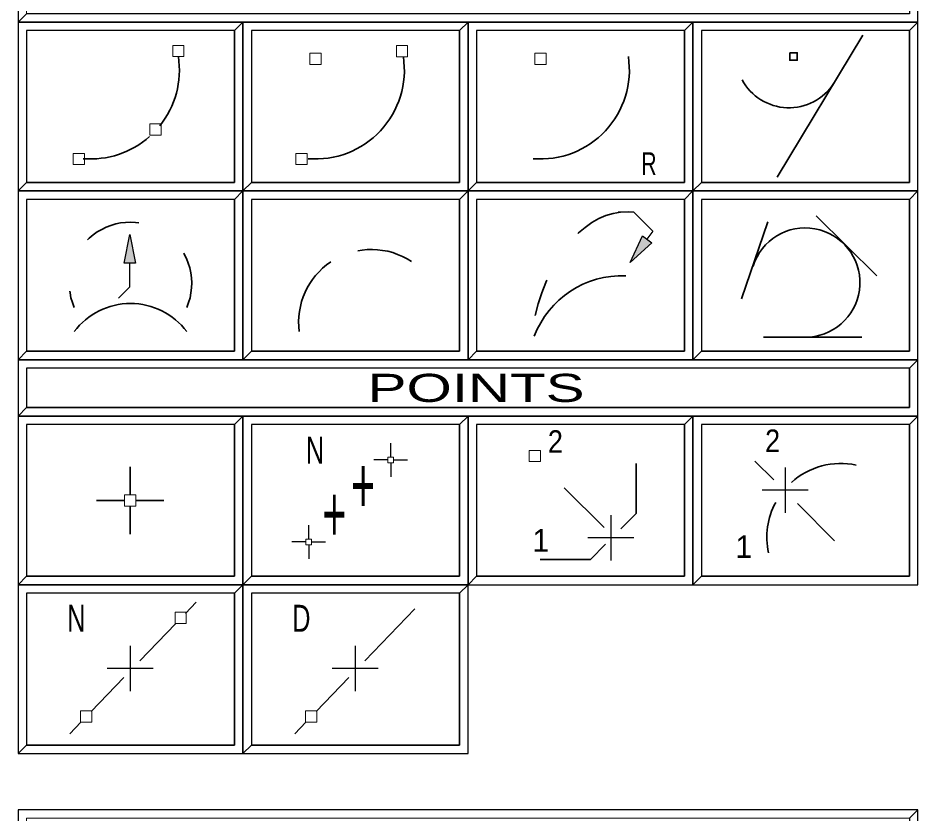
# Model space of a CAD drawing. Extents: x 95906.8 to 95923.6, y 90964.8 to 90972.8.
# Drawn here: x 95910.832 to 95912.432, y 90967.254 to 90968.669 of the extents above; entities that cross this region are included whole.
import ezdxf
from ezdxf.enums import TextEntityAlignment as Align

# ---------------------------------------------------------------- set-up
doc = ezdxf.new("R2010")
doc.units = 0
doc.header["$LTSCALE"] = 0.019
doc.linetypes.add('MEDIUM_DASHED', pattern=[4.5, 3, -1.5])
for name, color, linetype, lineweight in [('1', 7, 'Continuous', 25), ('11', 7, 'Continuous', 25), ('12', 7, 'Continuous', 25), ('17', 7, 'Continuous', 25), ('2', 7, 'Continuous', 13), ('3', 7, 'Continuous', 25), ('6', 7, 'Continuous', 35), ('7', 7, 'Continuous', 35)]:
    doc.layers.add(name, color=color, linetype=linetype, lineweight=lineweight)

msp = doc.modelspace()

# ---------------------------------------------------------------- hatches: boundary and pattern name
at = {"layer": '6'}
for points in [[(95911.0204, 90968.2331), (95911.0306, 90968.2843), (95911.0408, 90968.2331)], [(95911.9585, 90968.2697), (95911.92, 90968.2344), (95911.9421, 90968.2817)]]:
    msp.add_hatch(color=256, dxfattribs=at).paths.add_polyline_path(points)

# ---------------------------------------------------------------- linework, layer by layer
at = {"layer": '1'}
for points in [[(95910.8318, 90968.6617), (95912.4318, 90968.6617), (95912.4318, 90968.7617), (95910.8318, 90968.7617)], [(95910.8318, 90968.3617), (95911.2318, 90968.3617), (95911.2318, 90968.6617), (95910.8318, 90968.6617)], [(95911.2318, 90968.3617), (95911.6318, 90968.3617), (95911.6318, 90968.6617), (95911.2318, 90968.6617)], [(95911.6318, 90968.3617), (95912.0318, 90968.3617), (95912.0318, 90968.6617), (95911.6318, 90968.6617)], [(95912.0318, 90968.3617), (95912.4318, 90968.3617), (95912.4318, 90968.6617), (95912.0318, 90968.6617)], [(95910.8318, 90968.0617), (95911.2318, 90968.0617), (95911.2318, 90968.3617), (95910.8318, 90968.3617)], [(95911.2318, 90968.0617), (95911.6318, 90968.0617), (95911.6318, 90968.3617), (95911.2318, 90968.3617)], [(95911.6318, 90968.0617), (95912.0318, 90968.0617), (95912.0318, 90968.3617), (95911.6318, 90968.3617)], [(95912.0318, 90968.0617), (95912.4318, 90968.0617), (95912.4318, 90968.3617), (95912.0318, 90968.3617)], [(95910.8318, 90967.9617), (95912.4318, 90967.9617), (95912.4318, 90968.0617), (95910.8318, 90968.0617)], [(95910.8318, 90967.6617), (95911.2318, 90967.6617), (95911.2318, 90967.9617), (95910.8318, 90967.9617)], [(95911.2318, 90967.6617), (95911.6318, 90967.6617), (95911.6318, 90967.9617), (95911.2318, 90967.9617)], [(95911.6318, 90967.6617), (95912.0318, 90967.6617), (95912.0318, 90967.9617), (95911.6318, 90967.9617)], [(95912.0318, 90967.6617), (95912.4318, 90967.6617), (95912.4318, 90967.9617), (95912.0318, 90967.9617)], [(95910.8318, 90967.3617), (95911.2318, 90967.3617), (95911.2318, 90967.6617), (95910.8318, 90967.6617)], [(95911.2318, 90967.3617), (95911.6318, 90967.3617), (95911.6318, 90967.6617), (95911.2318, 90967.6617)], [(95910.8318, 90967.1617), (95912.4318, 90967.1617), (95912.4318, 90967.2617), (95910.8318, 90967.2617)]]:
    msp.add_lwpolyline(points, close=True, dxfattribs=at)
at = {"layer": '11'}
for points in [[(95911.2468, 90968.3767), (95911.6168, 90968.3767), (95911.6168, 90968.6467), (95911.2468, 90968.6467)], [(95911.6468, 90968.3767), (95912.0168, 90968.3767), (95912.0168, 90968.6467), (95911.6468, 90968.6467)], [(95912.0468, 90968.3767), (95912.4168, 90968.3767), (95912.4168, 90968.6467), (95912.0468, 90968.6467)], [(95910.8468, 90968.0767), (95911.2168, 90968.0767), (95911.2168, 90968.3467), (95910.8468, 90968.3467)], [(95911.2468, 90968.0767), (95911.6168, 90968.0767), (95911.6168, 90968.3467), (95911.2468, 90968.3467)], [(95911.6468, 90968.0767), (95912.0168, 90968.0767), (95912.0168, 90968.3467), (95911.6468, 90968.3467)], [(95912.0468, 90968.0767), (95912.4168, 90968.0767), (95912.4168, 90968.3467), (95912.0468, 90968.3467)], [(95911.2468, 90967.6767), (95911.6168, 90967.6767), (95911.6168, 90967.9467), (95911.2468, 90967.9467)], [(95911.6468, 90967.6767), (95912.0168, 90967.6767), (95912.0168, 90967.9467), (95911.6468, 90967.9467)], [(95912.0468, 90967.6767), (95912.4168, 90967.6767), (95912.4168, 90967.9467), (95912.0468, 90967.9467)], [(95910.8468, 90967.3767), (95911.2168, 90967.3767), (95911.2168, 90967.6467), (95910.8468, 90967.6467)], [(95911.2468, 90967.3767), (95911.6168, 90967.3767), (95911.6168, 90967.6467), (95911.2468, 90967.6467)]]:
    msp.add_lwpolyline(points, close=True, dxfattribs=at)
at = {"layer": '12'}
for points in [[(95910.8468, 90968.3767), (95911.2168, 90968.3767), (95911.2168, 90968.6467), (95910.8468, 90968.6467)], [(95910.8468, 90967.6767), (95911.2168, 90967.6767), (95911.2168, 90967.9467), (95910.8468, 90967.9467)]]:
    msp.add_lwpolyline(points, close=True, dxfattribs=at)
at = {"layer": '17'}
msp.add_lwpolyline([(95910.8468, 90967.9767), (95912.4168, 90967.9767), (95912.4168, 90968.0467), (95910.8468, 90968.0467)], close=True, dxfattribs=at)
at = {"layer": '2'}
for points in [[(95910.8318, 90968.7617), (95910.8318, 90968.6617), (95910.8468, 90968.6767), (95910.8468, 90968.7467), (95912.4168, 90968.7467), (95912.4318, 90968.7617)], [(95910.8318, 90968.6617), (95910.8318, 90968.3617), (95910.8468, 90968.3767), (95910.8468, 90968.6467), (95911.2168, 90968.6467), (95911.2318, 90968.6617)], [(95911.2318, 90968.6617), (95911.2318, 90968.3617), (95911.2468, 90968.3767), (95911.2468, 90968.6467), (95911.6168, 90968.6467), (95911.6318, 90968.6617)], [(95911.6318, 90968.6617), (95911.6318, 90968.3617), (95911.6468, 90968.3767), (95911.6468, 90968.6467), (95912.0168, 90968.6467), (95912.0318, 90968.6617)], [(95912.0318, 90968.6617), (95912.0318, 90968.3617), (95912.0468, 90968.3767), (95912.0468, 90968.6467), (95912.4168, 90968.6467), (95912.4318, 90968.6617)], [(95910.8318, 90968.3617), (95910.8318, 90968.0617), (95910.8468, 90968.0767), (95910.8468, 90968.3467), (95911.2168, 90968.3467), (95911.2318, 90968.3617)], [(95911.2318, 90968.3617), (95911.2318, 90968.0617), (95911.2468, 90968.0767), (95911.2468, 90968.3467), (95911.6168, 90968.3467), (95911.6318, 90968.3617)], [(95911.6318, 90968.3617), (95911.6318, 90968.0617), (95911.6468, 90968.0767), (95911.6468, 90968.3467), (95912.0168, 90968.3467), (95912.0318, 90968.3617)], [(95912.0318, 90968.3617), (95912.0318, 90968.0617), (95912.0468, 90968.0767), (95912.0468, 90968.3467), (95912.4168, 90968.3467), (95912.4318, 90968.3617)], [(95910.8318, 90968.0617), (95910.8318, 90967.9617), (95910.8468, 90967.9767), (95910.8468, 90968.0467), (95912.4168, 90968.0467), (95912.4318, 90968.0617)], [(95910.8318, 90967.9617), (95910.8318, 90967.6617), (95910.8468, 90967.6767), (95910.8468, 90967.9467), (95911.2168, 90967.9467), (95911.2318, 90967.9617)], [(95911.2318, 90967.9617), (95911.2318, 90967.6617), (95911.2468, 90967.6767), (95911.2468, 90967.9467), (95911.6168, 90967.9467), (95911.6318, 90967.9617)], [(95911.6318, 90967.9617), (95911.6318, 90967.6617), (95911.6468, 90967.6767), (95911.6468, 90967.9467), (95912.0168, 90967.9467), (95912.0318, 90967.9617)], [(95912.0318, 90967.9617), (95912.0318, 90967.6617), (95912.0468, 90967.6767), (95912.0468, 90967.9467), (95912.4168, 90967.9467), (95912.4318, 90967.9617)], [(95910.8318, 90967.6617), (95910.8318, 90967.3617), (95910.8468, 90967.3767), (95910.8468, 90967.6467), (95911.2168, 90967.6467), (95911.2318, 90967.6617)], [(95911.2318, 90967.6617), (95911.2318, 90967.3617), (95911.2468, 90967.3767), (95911.2468, 90967.6467), (95911.6168, 90967.6467), (95911.6318, 90967.6617)], [(95910.8318, 90967.2617), (95910.8318, 90967.1617), (95910.8468, 90967.1767), (95910.8468, 90967.2467), (95912.4168, 90967.2467), (95912.4318, 90967.2617)]]:
    msp.add_lwpolyline(points, close=True, dxfattribs=at)
at = {"layer": '3'}
for points in [[(95910.8318, 90968.6617), (95912.4318, 90968.6617), (95912.4318, 90968.7617), (95912.4168, 90968.7467), (95912.4168, 90968.6767), (95910.8468, 90968.6767)], [(95910.8318, 90968.3617), (95911.2318, 90968.3617), (95911.2318, 90968.6617), (95911.2168, 90968.6467), (95911.2168, 90968.3767), (95910.8468, 90968.3767)], [(95911.2318, 90968.3617), (95911.6318, 90968.3617), (95911.6318, 90968.6617), (95911.6168, 90968.6467), (95911.6168, 90968.3767), (95911.2468, 90968.3767)], [(95911.6318, 90968.3617), (95912.0318, 90968.3617), (95912.0318, 90968.6617), (95912.0168, 90968.6467), (95912.0168, 90968.3767), (95911.6468, 90968.3767)], [(95912.0318, 90968.3617), (95912.4318, 90968.3617), (95912.4318, 90968.6617), (95912.4168, 90968.6467), (95912.4168, 90968.3767), (95912.0468, 90968.3767)], [(95910.8318, 90968.0617), (95911.2318, 90968.0617), (95911.2318, 90968.3617), (95911.2168, 90968.3467), (95911.2168, 90968.0767), (95910.8468, 90968.0767)], [(95911.2318, 90968.0617), (95911.6318, 90968.0617), (95911.6318, 90968.3617), (95911.6168, 90968.3467), (95911.6168, 90968.0767), (95911.2468, 90968.0767)], [(95911.6318, 90968.0617), (95912.0318, 90968.0617), (95912.0318, 90968.3617), (95912.0168, 90968.3467), (95912.0168, 90968.0767), (95911.6468, 90968.0767)], [(95912.0318, 90968.0617), (95912.4318, 90968.0617), (95912.4318, 90968.3617), (95912.4168, 90968.3467), (95912.4168, 90968.0767), (95912.0468, 90968.0767)], [(95910.8318, 90967.9617), (95912.4318, 90967.9617), (95912.4318, 90968.0617), (95912.4168, 90968.0467), (95912.4168, 90967.9767), (95910.8468, 90967.9767)], [(95910.8318, 90967.6617), (95911.2318, 90967.6617), (95911.2318, 90967.9617), (95911.2168, 90967.9467), (95911.2168, 90967.6767), (95910.8468, 90967.6767)], [(95911.2318, 90967.6617), (95911.6318, 90967.6617), (95911.6318, 90967.9617), (95911.6168, 90967.9467), (95911.6168, 90967.6767), (95911.2468, 90967.6767)], [(95911.6318, 90967.6617), (95912.0318, 90967.6617), (95912.0318, 90967.9617), (95912.0168, 90967.9467), (95912.0168, 90967.6767), (95911.6468, 90967.6767)], [(95912.0318, 90967.6617), (95912.4318, 90967.6617), (95912.4318, 90967.9617), (95912.4168, 90967.9467), (95912.4168, 90967.6767), (95912.0468, 90967.6767)], [(95910.8318, 90967.3617), (95911.2318, 90967.3617), (95911.2318, 90967.6617), (95911.2168, 90967.6467), (95911.2168, 90967.3767), (95910.8468, 90967.3767)], [(95911.2318, 90967.3617), (95911.6318, 90967.3617), (95911.6318, 90967.6617), (95911.6168, 90967.6467), (95911.6168, 90967.3767), (95911.2468, 90967.3767)], [(95910.8318, 90967.1617), (95912.4318, 90967.1617), (95912.4318, 90967.2617), (95912.4168, 90967.2467), (95912.4168, 90967.1767), (95910.8468, 90967.1767)]]:
    msp.add_lwpolyline(points, close=True, dxfattribs=at)
at = {"layer": '6'}
for p, q in [((95912.1815, 90968.3864), (95912.334, 90968.6387)), ((95912.1182, 90968.1698), (95912.1646, 90968.3071)), ((95912.251, 90968.3178), (95912.3589, 90968.2108)), ((95912.3322, 90968.102), (95912.1574, 90968.102)), ((95912.142, 90967.8817), (95912.1756, 90967.8481)), ((95911.0312, 90967.8216), (95911.0312, 90967.8716)), ((95911.0212, 90967.8116), (95910.9712, 90967.8116)), ((95911.0412, 90967.8116), (95911.0912, 90967.8116)), ((95911.0312, 90967.8016), (95911.0312, 90967.7516)), ((95912.2836, 90967.74), (95912.2176, 90967.8061)), ((95911.1484, 90967.6305), (95911.1295, 90967.6108)), ((95911.4485, 90967.5266), (95911.537, 90967.6188)), ((95911.0485, 90967.5266), (95911.1117, 90967.5924)), ((95910.9617, 90967.4363), (95911.02, 90967.4969)), ((95911.3617, 90967.4363), (95911.42, 90967.4969)), ((95910.9238, 90967.3969), (95910.9434, 90967.4173)), ((95911.3238, 90967.3969), (95911.3434, 90967.4173))]:
    msp.add_line(p, q, dxfattribs=at)
at = {"layer": '6', "lineweight": 25}
for p, q in [((95911.4944, 90967.8886), (95911.4944, 90967.9136)), ((95911.4894, 90967.8836), (95911.4644, 90967.8836)), ((95911.4944, 90967.8786), (95911.4944, 90967.8536)), ((95911.4994, 90967.8836), (95911.5244, 90967.8836)), ((95912.1957, 90967.8699), (95912.1957, 90967.7896)), ((95912.1548, 90967.8305), (95912.2367, 90967.8305)), ((95911.8855, 90967.7853), (95911.8855, 90967.705)), ((95911.3486, 90967.7428), (95911.3486, 90967.7678)), ((95911.8446, 90967.7459), (95911.9265, 90967.7459)), ((95911.3436, 90967.7378), (95911.3186, 90967.7378)), ((95911.3486, 90967.7328), (95911.3486, 90967.7078)), ((95911.3536, 90967.7378), (95911.3786, 90967.7378)), ((95911.031, 90967.553), (95911.031, 90967.4727)), ((95911.431, 90967.553), (95911.431, 90967.4727)), ((95910.9901, 90967.5136), (95911.072, 90967.5136)), ((95911.3901, 90967.5136), (95911.472, 90967.5136))]:
    msp.add_line(p, q, dxfattribs=at)
at = {"layer": '6', "linetype": 'MEDIUM_DASHED'}
msp.add_line((95911.8738, 90967.7635), (95911.7588, 90967.8783), dxfattribs=at)
at = {"layer": '6', "lineweight": 13}
for points in [[(95911.1069, 90968.6005), (95911.1269, 90968.6005), (95911.1269, 90968.6205), (95911.1069, 90968.6205)], [(95911.5044, 90968.6001), (95911.5244, 90968.6001), (95911.5244, 90968.6201), (95911.5044, 90968.6201)], [(95911.3508, 90968.5865), (95911.3708, 90968.5865), (95911.3708, 90968.6065), (95911.3508, 90968.6065)], [(95911.7508, 90968.5865), (95911.7708, 90968.5865), (95911.7708, 90968.6065), (95911.7508, 90968.6065)], [(95911.0662, 90968.461), (95911.0862, 90968.461), (95911.0862, 90968.481), (95911.0662, 90968.481)], [(95910.9298, 90968.4086), (95910.9498, 90968.4086), (95910.9498, 90968.4286), (95910.9298, 90968.4286)], [(95911.326, 90968.4086), (95911.346, 90968.4086), (95911.346, 90968.4286), (95911.326, 90968.4286)], [(95911.4894, 90967.8786), (95911.4994, 90967.8786), (95911.4994, 90967.8886), (95911.4894, 90967.8886)], [(95911.7407, 90967.8806), (95911.7607, 90967.8806), (95911.7607, 90967.9006), (95911.7407, 90967.9006)], [(95911.0212, 90967.8016), (95911.0412, 90967.8016), (95911.0412, 90967.8216), (95911.0212, 90967.8216)], [(95911.3436, 90967.7328), (95911.3536, 90967.7328), (95911.3536, 90967.7428), (95911.3436, 90967.7428)], [(95911.111, 90967.5931), (95911.131, 90967.5931), (95911.131, 90967.6131), (95911.111, 90967.6131)], [(95910.9432, 90967.4175), (95910.9632, 90967.4175), (95910.9632, 90967.4375), (95910.9432, 90967.4375)], [(95911.3432, 90967.4175), (95911.3632, 90967.4175), (95911.3632, 90967.4375), (95911.3432, 90967.4375)]]:
    msp.add_lwpolyline(points, close=True, dxfattribs=at)
at = {"layer": '6'}
msp.add_lwpolyline([(95912.2038, 90968.6075), (95912.2172, 90968.6075), (95912.2172, 90968.5942), (95912.2038, 90968.5942)], close=True, dxfattribs=at)
at = {"layer": '6', "lineweight": 25}
for points in [[(95911.8989, 90968.3245), (95911.9258, 90968.3245), (95911.9603, 90968.29), (95911.95, 90968.2758)], [(95911.0105, 90968.1711), (95911.0306, 90968.1912), (95911.0306, 90968.2331)]]:
    msp.add_lwpolyline(points, dxfattribs=at)
for points in [[(95911.0204, 90968.2331), (95911.0306, 90968.2843), (95911.0408, 90968.2331)], [(95911.9585, 90968.2697), (95911.92, 90968.2344), (95911.9421, 90968.2817)]]:
    msp.add_lwpolyline(points, close=True, dxfattribs=at)
at = {"layer": '6'}
for points in [[(95911.9035, 90967.7609), (95911.9306, 90967.7881), (95911.9305, 90967.8772)], [(95911.8764, 90967.7338), (95911.8493, 90967.7067), (95911.7602, 90967.7067)]]:
    msp.add_lwpolyline(points, dxfattribs=at)
for centre, radius, start, end in [((95910.9608, 90968.5765), 0.1579, 321.1842, 8.7525), ((95911.3608, 90968.5765), 0.1579, 265.2424, 8.7525), ((95911.7608, 90968.5765), 0.1579, 265.2424, 8.7525), ((95912.2025, 90968.6043), 0.0947, 208.2947, 327.2812), ((95910.9608, 90968.5765), 0.1579, 265.2424, 311.6125), ((95912.2313, 90968.1989), 0.0972, 274.8279, 162.46), ((95911.4601, 90968.1283), 0.1294, 124.0311, 187.3672), ((95911.906, 90968.0437), 0.1674, 87.8498, 159.0411), ((95911.0318, 90968.0367), 0.125, 36.8699, 143.1301), ((95912.2948, 90967.7457), 0.1317, 78.0876, 132.0346), ((95912.2948, 90967.7457), 0.1317, 151.6888, 191.9492)]:
    msp.add_arc(centre, radius, start, end, dxfattribs=at)
at = {"layer": '6', "linetype": 'MEDIUM_DASHED'}
for centre, radius, start, end in [((95911.0318, 90968.1975), 0.1088, 336.7954, 203.2046), ((95911.4602, 90968.1282), 0.1295, 56.5459, 121.945)]:
    msp.add_arc(centre, radius, start, end, dxfattribs=at)
msp.add_ellipse((95911.906, 90968.0437), major_axis=(0.0105, 0.2807), ratio=0.595849, start_param=6.283185, end_param=7.525708, dxfattribs=at)

# ---------------------------------------------------------------- texts
at = {"layer": '6'}
for s, height, width, p in [('R', 0.04, 0.7, (95911.9535, 90968.3904)), ('2', 0.04, 0.9, (95911.7872, 90967.8963)), ('2', 0.04, 0.9, (95912.1733, 90967.8977)), ('N', 0.048, 0.7, (95911.3599, 90967.8769)), ('+', 0.1, 0.55, (95911.4453, 90967.789)), ('+', 0.1, 0.55, (95911.3942, 90967.738)), ('N', 0.048, 0.7, (95910.9355, 90967.5781)), ('D', 0.048, 0.7, (95911.3355, 90967.5781))]:
    msp.add_text(s, height=height, dxfattribs=dict(at, width=width)).set_placement(p, align=Align.CENTER)
for p in [(95911.7612, 90967.7206), (95912.1222, 90967.7095)]:
    msp.add_text('1', height=0.04, dxfattribs=at).set_placement(p, align=Align.CENTER)
at = {"layer": '7', "width": 1.55}
msp.add_text('         POINTS        ', height=0.04999, dxfattribs=at).set_placement((95911.6318, 90967.9867), align=Align.CENTER)

doc.saveas('drawing.dxf')
